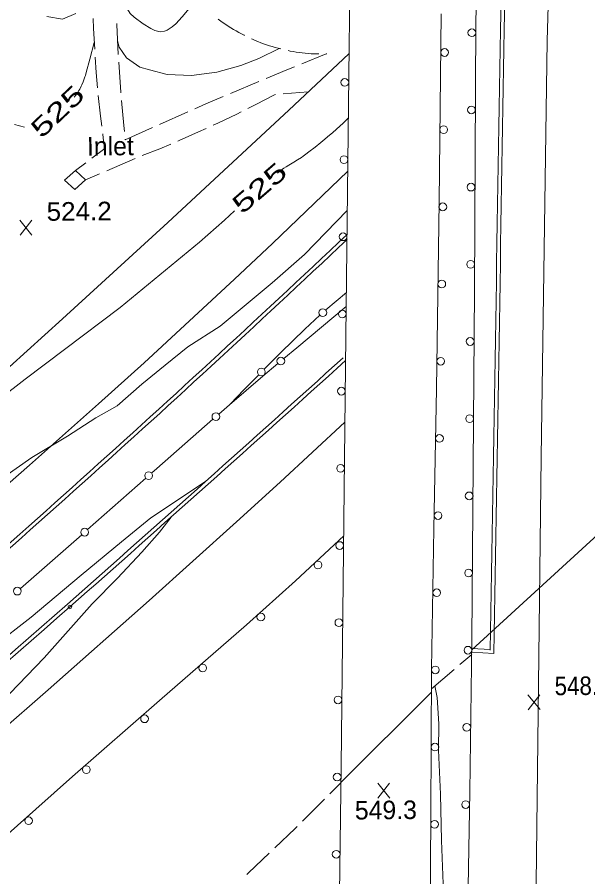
# Model space of a CAD drawing. Extents: x 2361284 to 2366480, y 6976556 to 6985346.
# Drawn here: x 2364334.6 to 2364482.3, y 6979084.2 to 6979307 of the extents above; entities that cross this region are included whole.
import ezdxf
from ezdxf.enums import TextEntityAlignment as Align

# ---------------------------------------------------------------- set-up
doc = ezdxf.new("R2010")
doc.units = 0
doc.header["$LTSCALE"] = 1.9
doc.header["$PDMODE"] = 32
doc.header["$PDSIZE"] = 0.95
for name, color, linetype, lineweight in [('12', 7, 'Continuous', 13), ('13', 7, 'Continuous', 13), ('14', 7, 'Continuous', 13), ('17', 7, 'Continuous', 13), ('24', 7, 'Continuous', 13), ('3', 7, 'Continuous', 13), ('5', 7, 'Continuous', 13), ('6', 7, 'Continuous', 13), ('8', 7, 'Continuous', 13)]:
    doc.layers.add(name, color=color, linetype=linetype, lineweight=lineweight)

msp = doc.modelspace()

# ---------------------------------------------------------------- linework, layer by layer
at = {"layer": '12'}
for p, q in [((2364338.429, 6979250.497), (2364335.312, 6979254.348)), ((2364335.349, 6979250.468), (2364338.392, 6979254.377)), ((2364469.934, 6979127.561), (2364466.817, 6979131.412)), ((2364466.854, 6979127.532), (2364469.897, 6979131.441)), ((2364431.051, 6979104.63), (2364427.934, 6979108.481)), ((2364427.971, 6979104.601), (2364431.014, 6979108.51))]:
    msp.add_line(p, q, dxfattribs=at)
for points in [[(2364354.549, 6979300.411), (2364353.37, 6979296.06), (2364352.453, 6979292.631), (2364352.248, 6979291.912), (2364352.138, 6979291.554), (2364351.962, 6979291.022), (2364351.671, 6979290.231), (2364351.346, 6979289.454), (2364351.17, 6979289.07), (2364350.788, 6979288.316), (2364350.582, 6979287.946), (2364350.252, 6979287.399), (2364349.983, 6979287.007), (2364349.792, 6979286.758), (2364349.393, 6979286.271)], [(2364360.594, 6979300.969), (2364361, 6979299.253), (2364362.917, 6979296.481), (2364366.331, 6979294.013), (2364368.848, 6979293.317), (2364373.399, 6979292.139), (2364379.722, 6979291.829), (2364386.323, 6979292.743), (2364392.498, 6979294.432), (2364397.121, 6979296.246), (2364402.417, 6979298.856)], [(2364420.309, 6979280.775), (2364418.986, 6979279.534), (2364418.093, 6979278.721), (2364416.284, 6979277.117), (2364414.943, 6979275.962), (2364414.266, 6979275.392), (2364413.244, 6979274.546), (2364411.693, 6979273.301), (2364410.12, 6979272.081), (2364409.326, 6979271.481), (2364408.629, 6979270.981), (2364408.155, 6979270.661), (2364407.191, 6979270.045), (2364406.214, 6979269.448), (2364404.912, 6979268.652), (2364404.268, 6979268.243), (2364403.633, 6979267.821), (2364403.32, 6979267.604), (2364402.857, 6979267.268), (2364402.268, 6979266.811), (2364401.984, 6979266.57)], [(2364336.526, 6979278.509), (2364333.93, 6979279.194)], [(2364390.836, 6979256.813), (2364388.279, 6979254.359), (2364381.782, 6979248.668), (2364361.222, 6979231.731), (2364346.825, 6979220.903), (2364336.657, 6979213.196), (2364322.68, 6979202.352), (2364301.098, 6979184.517), (2364286.575, 6979173.257), (2364271.051, 6979161.92), (2364257.258, 6979150.698), (2364242.084, 6979137.233), (2364226.838, 6979123.107), (2364209.815, 6979105.355), (2364202.006, 6979096.9), (2364190.718, 6979085.091), (2364175.717, 6979070.308)]]:
    msp.add_lwpolyline(points, dxfattribs=at)
at = {"layer": '13'}
for points in [[(2364359.994, 6979330.345), (2364360.386, 6979328.53), (2364360.786, 6979324.892), (2364361.669, 6979315.18), (2364361.99, 6979312.705), (2364362.244, 6979311.481), (2364362.821, 6979309.66), (2364363.117, 6979309.031), (2364363.887, 6979307.937), (2364364.854, 6979306.998), (2364367.174, 6979305.292), (2364369.198, 6979304.005), (2364370.214, 6979303.537), (2364371.233, 6979303.258), (2364371.744, 6979303.205), (2364372.74, 6979303.344), (2364373.409, 6979303.609), (2364374.712, 6979304.443), (2364375.677, 6979305.284), (2364377.277, 6979307.038), (2364379.532, 6979309.708), (2364380.954, 6979311.542)], [(2364349.777, 6979307.895), (2364346.362, 6979306.494), (2364342.284, 6979307.175)], [(2364420.046, 6979256.901), (2364408.964, 6979245.465), (2364400.564, 6979238.125), (2364393.877, 6979232.521), (2364387.179, 6979226.927), (2364378.749, 6979221.577), (2364372.915, 6979216.821), (2364366.862, 6979211.913), (2364360.454, 6979206.302), (2364354.974, 6979203.149), (2364347.639, 6979198.459), (2364338.371, 6979192.852), (2364327.899, 6979185.592)], [(2364189.118, 6979049.315), (2364193.41, 6979051.236), (2364198.573, 6979053.035), (2364202.826, 6979054.845), (2364209.687, 6979057.9), (2364216.613, 6979061.546), (2364222.309, 6979065.07), (2364230.397, 6979070.598), (2364235.205, 6979074.095), (2364246.626, 6979081.363), (2364254.275, 6979086.755), (2364264.493, 6979094.404), (2364273.377, 6979101.289), (2364290.551, 6979115.803), (2364301.095, 6979123.833), (2364309.142, 6979129.48), (2364318.822, 6979136.882), (2364328.426, 6979143.884), (2364338.213, 6979151.557), (2364351.171, 6979162.372), (2364361.579, 6979171.05), (2364369.221, 6979177.283), (2364383.332, 6979186.649)], [(2364374.42, 6979177.413), (2364371.437, 6979173.564), (2364366.886, 6979168.361), (2364360.579, 6979161.601), (2364353.982, 6979154.957), (2364341.554, 6979140.949), (2364332.732, 6979131.734), (2364325.931, 6979124.399), (2364320.317, 6979118.526), (2364312.96, 6979111.774), (2364304.036, 6979102.7), (2364292.967, 6979092.024), (2364266.46, 6979069.42), (2364249.398, 6979054.798), (2364237.122, 6979043.94), (2364227.83, 6979036.592), (2364213.456, 6979024.384), (2364191.149, 6979005.012), (2364177.88, 6978993.245), (2364169.265, 6978985.383), (2364155.723, 6978972.782), (2364142.669, 6978960.479)], [(2364442.728, 6979133.74), (2364443.308, 6979130.686), (2364443.732, 6979123.889), (2364443.697, 6979117.019), (2364444.166, 6979105.623), (2364444.439, 6979093.695), (2364444.978, 6979080.169), (2364444.254, 6979063.751), (2364443.482, 6979051.334), (2364444.106, 6979043.508), (2364444.802, 6979032.394), (2364446.061, 6979019.866), (2364447.477, 6979009.849), (2364450.466, 6978997.307)]]:
    msp.add_lwpolyline(points, dxfattribs=at)
at = {"layer": '14'}
for points in [[(2364788.322, 6980235.427), (2364751.681, 6980173.335), (2364672.902, 6980040.208), (2364634.711, 6979971.851), (2364622.071, 6979947.18), (2364598.761, 6979896.866), (2364567.538, 6979821.813), (2364553.395, 6979783.669), (2364537.103, 6979734.874), (2364529.681, 6979710.276), (2364519.464, 6979673.08), (2364501.297, 6979593.872), (2364491.081, 6979538.866), (2364486.722, 6979511.209), (2364479.824, 6979459.469), (2364477.138, 6979433.54), (2364474.49, 6979394.536), (2364471.751, 6979300.826)], [(2364471.751, 6979300.826), (2364470.266, 6979192.976), (2364468.687, 6979060.443), (2364467.19, 6978950.713), (2364465.398, 6978823.599), (2364465.014, 6978782.341), (2364464.713, 6978727.329), (2364464.476, 6978699.823), (2364463.104, 6978583.283), (2364461.505, 6978460.062), (2364461.304, 6978437.786), (2364461.091, 6978393.234)], [(2364420.159, 6979267.113), (2364400.723, 6979248.336), (2364390.885, 6979239.073), (2364367.462, 6979217.462), (2364355.655, 6979206.764), (2364337.799, 6979190.876), (2364315.598, 6979171.486), (2364300.731, 6979158.638), (2364270.855, 6979133.106), (2364244.209, 6979110.62), (2364230.829, 6979099.447), (2364210.669, 6979082.791), (2364189.937, 6979065.945), (2364176.031, 6979054.822), (2364148.013, 6979032.833), (2364126.906, 6979016.585), (2364112.779, 6979005.83), (2364084.388, 6978984.496), (2364056.021, 6978963.478), (2364041.79, 6978953.033), (2364020.372, 6978937.464), (2363990.222, 6978915.934), (2363975.045, 6978905.311), (2363972.005, 6978903.232)], [(2363951.494, 6978832.723), (2363965.118, 6978841.916), (2363992.242, 6978860.482), (2364021.619, 6978880.939), (2364036.247, 6978891.253), (2364058.115, 6978906.831), (2364078.805, 6978921.811), (2364092.528, 6978931.892), (2364119.847, 6978952.23), (2364146.002, 6978972.008), (2364163.349, 6978985.309), (2364197.851, 6979012.166), (2364222.356, 6979031.614), (2364234.536, 6979041.425), (2364252.715, 6979056.252), (2364279.783, 6979078.749), (2364309.686, 6979104.155), (2364329.473, 6979121.256), (2364342.603, 6979132.728), (2364368.725, 6979155.838), (2364391.388, 6979176.238), (2364402.645, 6979186.517), (2364419.438, 6979202.042)]]:
    msp.add_lwpolyline(points, dxfattribs=at)
at = {"layer": '17'}
for points in [[(2364453.304, 6979305.691), (2364453.989, 6979333.598), (2364454.945, 6979361.5), (2364455.701, 6979375.577), (2364456.507, 6979389.646), (2364456.823, 6979397.478), (2364457.098, 6979405.312), (2364457.467, 6979425.427), (2364457.846, 6979445.541), (2364459.079, 6979467.134), (2364461.385, 6979488.637), (2364464.031, 6979508.033), (2364466.717, 6979527.42), (2364468.167, 6979537.864), (2364469.628, 6979548.309)], [(2364417.758, 6979060.079), (2364418.136, 6979086.513), (2364418.465, 6979112.948), (2364419.076, 6979168.637), (2364419.686, 6979224.326), (2364420.178, 6979269.333), (2364420.68, 6979314.33)], [(2364444.353, 6979307.846), (2364443.795, 6979259.247), (2364443.147, 6979210.649), (2364442.492, 6979174.41), (2364441.856, 6979138.163), (2364441.648, 6979100.168), (2364441.439, 6979062.174), (2364441.005, 6979028.918), (2364440.571, 6978995.663), (2364440.44, 6978986.341), (2364440.319, 6978977.008), (2364439.788, 6978919.211), (2364439.328, 6978861.403), (2364438.813, 6978806.165), (2364438.298, 6978750.917), (2364438.11, 6978727.544), (2364437.983, 6978704.162), (2364438.297, 6978676.313), (2364438.802, 6978648.466), (2364438.849, 6978604.574), (2364438.917, 6978560.692), (2364439.979, 6978526.851), (2364441.96, 6978493.038)], [(2364446.359, 6978672.98), (2364446.68, 6978699.164), (2364446.981, 6978725.358), (2364447.359, 6978766.605), (2364447.757, 6978807.84), (2364448.554, 6978870.221), (2364449.441, 6978932.593), (2364449.946, 6978963.65), (2364450.441, 6978994.716), (2364450.787, 6979030.811), (2364451.104, 6979066.906), (2364451.74, 6979106.275), (2364452.316, 6979145.642), (2364452.656, 6979190.848), (2364452.936, 6979236.063), (2364453.125, 6979270.877), (2364453.304, 6979305.691)], [(2364419.118, 6979172.568), (2364406.627, 6979160.979), (2364393.976, 6979149.567), (2364371.442, 6979129.902), (2364348.918, 6979110.207), (2364334.677, 6979097.561), (2364320.436, 6979084.904), (2364311.928, 6979077.354), (2364303.419, 6979069.802), (2364297.588, 6979064.496), (2364291.84, 6979059.101)]]:
    msp.add_lwpolyline(points, dxfattribs=at)
for centre in [(2364452.29, 6979302.948), (2364445.238, 6979297.834), (2364419.412, 6979290.077), (2364452.189, 6979282.948), (2364445.009, 6979277.836), (2364419.191, 6979270.078), (2364452.085, 6979262.949), (2364444.776, 6979257.835), (2364418.97, 6979250.079), (2364451.974, 6979242.949), (2364444.51, 6979237.836), (2364418.749, 6979230.08), (2364451.856, 6979222.95), (2364444.243, 6979217.838), (2364418.53, 6979210.081), (2364451.735, 6979202.95), (2364443.916, 6979197.836), (2364418.31, 6979190.082), (2364451.601, 6979182.952), (2364443.555, 6979177.839), (2364418.091, 6979170.083), (2364412.465, 6979165.036), (2364451.448, 6979162.952), (2364443.202, 6979157.842), (2364397.672, 6979151.557), (2364417.872, 6979150.084), (2364451.277, 6979142.96), (2364382.636, 6979138.344), (2364442.855, 6979137.857), (2364417.653, 6979130.085), (2364367.571, 6979125.189), (2364450.986, 6979122.962), (2364442.745, 6979117.857), (2364352.515, 6979112.025), (2364417.429, 6979110.087), (2364450.69, 6979102.965), (2364337.548, 6979098.77), (2364442.636, 6979097.857), (2364417.178, 6979090.089)]:
    msp.add_circle(centre, 1, dxfattribs=at)
at = {"layer": '24'}
for p, q in [((2364408.264, 6979294.892), (2364414.591, 6979297.462)), ((2364414.691, 6979297.463), (2364414.781, 6979297.464)), ((2364389.797, 6979287.195), (2364397.178, 6979290.295)), ((2364371.472, 6979279.181), (2364378.781, 6979282.44)), ((2364452.252, 6979141.821), (2364449.207, 6979139.233)), ((2364447.679, 6979137.939), (2364441.826, 6979132.972)), ((2364418.406, 6979108.588), (2364415.573, 6979105.761)), ((2364414.157, 6979104.347), (2364408.499, 6979098.693))]:
    msp.add_line(p, q, dxfattribs=at)
for points in [[(2364360.412, 6979305.317), (2364360.425, 6979305.088), (2364360.778, 6979297.331)], [(2364386.663, 6979306.447), (2364387.297, 6979305.983), (2364387.942, 6979305.519), (2364388.597, 6979305.075), (2364389.251, 6979304.652), (2364389.915, 6979304.218), (2364390.589, 6979303.814), (2364391.273, 6979303.411), (2364391.957, 6979303.027), (2364392.65, 6979302.654), (2364393.344, 6979302.29), (2364393.454, 6979302.231)], [(2364395.262, 6979301.379), (2364395.473, 6979301.281), (2364396.206, 6979300.958), (2364396.929, 6979300.664), (2364397.662, 6979300.371), (2364398.395, 6979300.098), (2364399.147, 6979299.835), (2364399.89, 6979299.592), (2364400.642, 6979299.36), (2364401.394, 6979299.137), (2364402.156, 6979298.924), (2364402.808, 6979298.76)], [(2364404.751, 6979298.309), (2364405.232, 6979298.213), (2364406.003, 6979298.081), (2364406.775, 6979297.948), (2364407.556, 6979297.825), (2364408.337, 6979297.733), (2364409.118, 6979297.64), (2364409.908, 6979297.568), (2364410.69, 6979297.505), (2364410.99, 6979297.488), (2364412.69, 6979297.474)], [(2364360.897, 6979295.332), (2364361.431, 6979287.565), (2364361.453, 6979287.345)], [(2364399.021, 6979291.073), (2364404.398, 6979293.325), (2364406.411, 6979294.144)], [(2364361.632, 6979285.357), (2364362.194, 6979278.883), (2364362.338, 6979277.384)], [(2364380.603, 6979283.257), (2364383.421, 6979284.514), (2364387.953, 6979286.417)], [(2364362.517, 6979275.396), (2364362.539, 6979275.186), (2364369.65, 6979278.364)], [(2364407.083, 6979097.28), (2364406.567, 6979096.765), (2364401.306, 6979091.754)], [(2364399.859, 6979090.37), (2364394.517, 6979085.289), (2364394.051, 6979084.864)]]:
    msp.add_lwpolyline(points, dxfattribs=at)
at = {"layer": '3'}
for p, q in [((2364347.615, 6979154.884), (2364347.613, 6979154.882)), ((2364452.327, 6979143.412), (2364457.041, 6979143.107))]:
    msp.add_line(p, q, dxfattribs=at)
for points in [[(2364459.673, 6979303.741), (2364461.803, 6979400.476), (2364461.804, 6979400.464)], [(2364460.633, 6979303.72), (2364462.763, 6979400.455), (2364462.764, 6979400.455)], [(2364420.49, 6979297.498), (2364404.923, 6979282.861), (2364373.594, 6979253.799), (2364346.336, 6979228.833), (2364332.644, 6979216.423), (2364312.02, 6979197.901), (2364280.872, 6979170.343), (2364270.685, 6979161.47), (2364250.157, 6979143.91), (2364229.44, 6979126.579), (2364215.532, 6979115.14), (2364187.506, 6979092.511), (2364159.353, 6979070.211), (2364140.495, 6979055.466), (2364127.883, 6979045.688), (2364102.562, 6979026.249), (2364070.367, 6979001.877), (2364054.195, 6978989.794), (2364029.815, 6978971.825), (2364003.059, 6978952.52), (2363985.107, 6978939.817), (2363973.091, 6978931.414), (2363948.954, 6978914.753)], [(2364452.266, 6979142.451), (2364457.961, 6979142.085), (2364457.96, 6979142.084)]]:
    msp.add_lwpolyline(points, dxfattribs=at)
for centre, radius, start, end in [((2281749.446, 6980590.861), 82720.242, 358.99706, 359.10844), ((2281654.782, 6980592.426), 82815.879, 358.99654, 359.10838), ((2361885.12, 6981930.042), 3688.416, 310.40774, 313.41262), ((2361884.964, 6981930.216), 3689.61, 310.40784, 313.39897), ((2358687.847, 6985553.547), 8542.591, 311.4935, 312.13567), ((2358687.847, 6985553.547), 8543.551, 311.4935, 312.13567), ((2361757.968, 6982101.757), 3923.052, 307.14611, 311.3083), ((2361757.968, 6982101.757), 3924.012, 307.14611, 311.3083)]:
    msp.add_arc(centre, radius, start, end, dxfattribs=at)
msp.add_point((2364348.249, 6979154.163), dxfattribs=at)
at = {"layer": '5'}
for p, q in [((2364414.491, 6979231.117), (2364419.809, 6979235.618)), ((2364352.819, 6979174.197), (2364367.904, 6979187.532)), ((2364335.443, 6979158.971), (2364351.321, 6979172.883))]:
    msp.add_line(p, q, dxfattribs=at)
for points in [[(2364403.65, 6979218.544), (2364406.973, 6979221.335), (2364413.363, 6979226.686), (2364419.773, 6979232.017)], [(2364398.507, 6979215.755), (2364402.845, 6979220.126), (2364409.017, 6979226.145), (2364412.974, 6979229.743)], [(2364386.786, 6979204.143), (2364389.544, 6979206.569), (2364398.223, 6979213.992), (2364402.083, 6979217.229)], [(2364389.841, 6979206.822), (2364393.297, 6979210.425), (2364396.773, 6979214.008), (2364397.11, 6979214.341)], [(2364369.441, 6979188.887), (2364370.79, 6979190.08), (2364385.288, 6979202.827)]]:
    msp.add_lwpolyline(points, dxfattribs=at)
for centre in [(2364413.714, 6979230.425), (2364402.843, 6979217.868), (2364397.812, 6979215.055), (2364386.037, 6979203.486), (2364368.649, 6979188.188), (2364352.073, 6979173.54), (2364334.657, 6979158.273)]:
    msp.add_circle(centre, 1, dxfattribs=at)
at = {"layer": '6'}
for p, q in [((2364403.469, 6979287.085), (2364409.942, 6979287.677)), ((2364352.335, 6979269.258), (2364349.684, 6979267.273)), ((2364357.765, 6979267.2), (2364365.125, 6979270.341)), ((2364352.247, 6979264.837), (2364355.922, 6979266.412))]:
    msp.add_line(p, q, dxfattribs=at)
for points in [[(2364354.26, 6979306.639), (2364354.354, 6979304.08), (2364354.666, 6979298.652)], [(2364354.795, 6979296.654), (2364355.052, 6979292.686), (2364355.41, 6979288.678)], [(2364394.344, 6979283.338), (2364396.334, 6979284.347), (2364401.181, 6979286.883), (2364401.48, 6979286.906)], [(2364355.599, 6979286.69), (2364356.18, 6979281.345), (2364356.505, 6979278.739)], [(2364385.354, 6979278.963), (2364386.549, 6979279.515), (2364391.478, 6979281.891), (2364392.562, 6979282.441)], [(2364376.222, 6979274.886), (2364376.571, 6979275.03), (2364381.56, 6979277.237), (2364383.532, 6979278.136)], [(2364356.744, 6979276.751), (2364356.884, 6979275.643), (2364357.26, 6979272.946), (2364353.934, 6979270.454)], [(2364366.969, 6979271.108), (2364371.552, 6979272.912), (2364374.381, 6979274.109)]]:
    msp.add_lwpolyline(points, dxfattribs=at)
at = {"layer": '8'}
for p, q in [((2364485.96, 6979173.863), (2364452.281, 6979143.032)), ((2364441.824, 6979132.122), (2364418.406, 6979108.688))]:
    msp.add_line(p, q, dxfattribs=at)
msp.add_lwpolyline([(2364352.257, 6979264.827), (2364349.674, 6979267.283), (2364346.839, 6979264.736), (2364349.511, 6979262.331)], close=True, dxfattribs=at)

# ---------------------------------------------------------------- texts
at = {"layer": '12', "width": 1.5}
for height, rotation, p in [(4.799, 43.53, (2364346.688, 6979280.854)), (4.8, 40.803, (2364398.883, 6979260.954))]:
    msp.add_text(' 525 ', height=height, rotation=rotation, dxfattribs=at).set_placement(p, align=Align.CENTER)
at = {"layer": '12'}
for s, width, p in [('524.2', 1.05, (2364342.237, 6979254.221)), ('548.1', 0.9, (2364473.743, 6979131.285))]:
    msp.add_text(s, height=4.799, rotation=0.545, dxfattribs=dict(at, width=width)).set_placement(p)
msp.add_text('549.3', height=4.799, rotation=0.545, dxfattribs=at).set_placement((2364422.027, 6979099.082))
at = {"layer": '8'}
msp.add_text('Inlet', height=4.799, rotation=0.545, dxfattribs=at).set_placement((2364352.677, 6979271.112))

doc.saveas('drawing.dxf')
